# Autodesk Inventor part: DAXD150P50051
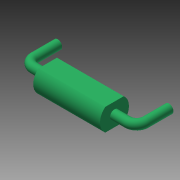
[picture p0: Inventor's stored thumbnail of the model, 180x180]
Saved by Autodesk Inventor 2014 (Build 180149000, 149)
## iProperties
Shininess: 64.0
Length Units: 11272
Angle Units: 11279
Time Units: 11290
Mass Units: 11286
Length Display Precision: 3
Angle Display Precision: 2
Compacted: True
Part Number: DAXD150P50051
Document SubType Name: Modeling
Created: 2003-04
Designer: t_enrig
Manufacturer: Standard
Standards Organization: Custom
Density: 1 g/cm^3
Mass: 0.0662591 g
Surface Area: 1.2819 cm^2
Volume: 0.0662591 cm^3
Material: Generic
Appearance: TranslatedColorStyle
Density: 0.0
Volumn: 0.0
Area: 0.0
PropertySet Name: Model Information
Control State: 0
Master: False
Checked Out: False
Author: t_enrig
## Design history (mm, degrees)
feature "Base1"
body "Solid1"
